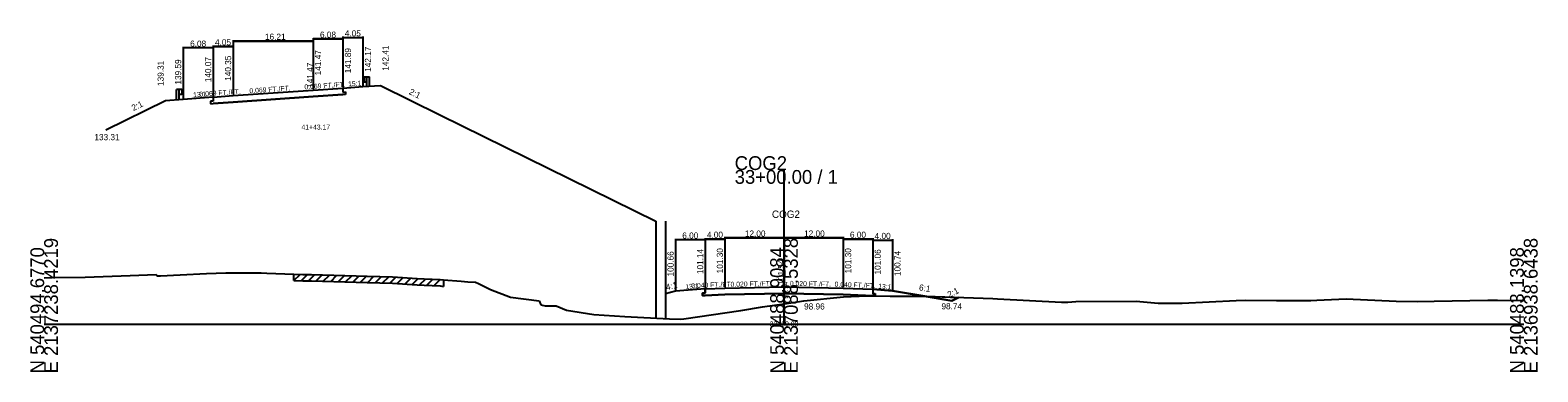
# Model space of a CAD drawing. Extents: x -13397 to 2303, y -10 to 39059.
# Drawn here: x 997.2 to 1302.8, y 5990.3 to 6059.6 of the extents above; entities that cross this region are included whole.
import ezdxf

# ---------------------------------------------------------------- set-up
doc = ezdxf.new("R2010")
doc.units = 0
for name, color, linetype in [('Level 20', 7, 'Continuous'), ('Level 5', 7, 'Continuous'), ('Level 53', 7, 'Continuous'), ('Level 54', 7, 'Continuous'), ('Level 55', 7, 'Continuous'), ('Level 7', 7, 'Continuous'), ('RD_GPK_XS_Cell', 7, 'Continuous'), ('RD_XS_EwShp', 7, 'Continuous'), ('RD_XS_ExGround', 7, 'Continuous'), ('RD_XS_ExPaveRet', 7, 'Continuous'), ('RD_XS_MedBWall', 7, 'Continuous'), ('RD_XS_Pave', 7, 'Continuous'), ('RD_XS_TX_Baseline', 7, 'Continuous'), ('RD_XS_TX_Elev_EX', 7, 'Continuous'), ('RD_XS_TX_Elev_PR', 7, 'Continuous'), ('RD_XS_TX_Station', 7, 'Continuous')]:
    doc.layers.add(name, color=color, linetype=linetype)

msp = doc.modelspace()

# ---------------------------------------------------------------- linework, layer by layer
at = {"layer": 'Level 20'}
for p, q in [((1028.17, 6056.22), (1028.17, 6045.79)), ((1034.25, 6056.02), (1028.17, 6056.02)), ((1034.25, 6056.5), (1034.25, 6046.27)), ((1034.25, 6056.5), (1034.25, 6046.27)), ((1034.25, 6056.5), (1034.25, 6046.27)), ((1034.25, 6056.3), (1038.3, 6056.3)), ((1034.25, 6056.3), (1038.3, 6056.3)), ((1038.3, 6056.3), (1034.25, 6056.3)), ((1034.25, 6056.22), (1034.25, 6046.27)), ((1038.3, 6057.62), (1038.3, 6046.55)), ((1038.3, 6057.62), (1038.3, 6046.55)), ((1038.3, 6057.62), (1038.3, 6046.55)), ((1038.3, 6057.62), (1038.3, 6046.55)), ((1038.3, 6057.42), (1054.51, 6057.42)), ((1038.3, 6057.42), (1054.51, 6057.42)), ((1054.51, 6057.42), (1038.3, 6057.42)), ((1054.51, 6057.42), (1038.3, 6057.42)), ((1038.3, 6056.5), (1038.3, 6046.55)), ((1038.3, 6056.5), (1038.3, 6046.55)), ((1038.3, 6056.5), (1038.3, 6046.55)), ((1054.51, 6058.04), (1054.51, 6047.67)), ((1054.51, 6058.04), (1054.51, 6047.67)), ((1054.51, 6058.04), (1054.51, 6047.67)), ((1054.51, 6057.84), (1060.58, 6057.84)), ((1060.58, 6057.84), (1054.51, 6057.84)), ((1060.58, 6057.84), (1054.51, 6057.84)), ((1054.51, 6057.62), (1054.51, 6047.67)), ((1054.51, 6057.62), (1054.51, 6047.67)), ((1054.51, 6057.62), (1054.51, 6047.67)), ((1054.51, 6057.62), (1054.51, 6047.67)), ((1060.58, 6058.32), (1060.58, 6048.09)), ((1060.58, 6058.12), (1064.63, 6058.12)), ((1060.58, 6058.04), (1060.58, 6048.09)), ((1060.58, 6058.04), (1060.58, 6048.09)), ((1060.58, 6058.04), (1060.58, 6048.09)), ((1064.63, 6058.32), (1064.63, 6048.37)), ((1064.66, 6049.99), (1064.77, 6050.08)), ((1064.66, 6049.88), (1064.77, 6049.79)), ((1064.66, 6049.46), (1064.77, 6049.55)), ((1064.79, 6050.08), (1064.86, 6050.1)), ((1064.79, 6049.75), (1064.79, 6049.59)), ((1064.86, 6050.16), (1064.86, 6049.18)), ((1064.86, 6050.16), (1065.42, 6050.16)), ((1065.42, 6048.17), (1065.42, 6050.16)), ((1065.42, 6050.16), (1065.97, 6050.16)), ((1065.97, 6048.17), (1065.97, 6050.16)), ((1026.83, 6045.59), (1026.83, 6047.58)), ((1027.39, 6047.58), (1026.83, 6047.58)), ((1027.39, 6045.59), (1027.39, 6047.58)), ((1027.94, 6047.58), (1027.39, 6047.58)), ((1027.94, 6046.6), (1027.39, 6046.6)), ((1027.94, 6047.58), (1027.94, 6046.6)), ((1028.02, 6047.5), (1027.94, 6047.52)), ((1028.02, 6046.68), (1027.94, 6046.66)), ((1028.01, 6047.17), (1028.01, 6047.01)), ((1028.15, 6047.41), (1028.03, 6047.5)), ((1028.15, 6047.3), (1028.03, 6047.21)), ((1028.15, 6046.88), (1028.03, 6046.97)), ((1028.15, 6046.77), (1028.03, 6046.68)), ((1038.3, 6046.35), (1054.51, 6047.47)), ((1054.51, 6047.47), (1060.58, 6047.89)), ((1060.58, 6046.56), (1054.51, 6046.14)), ((1054.51, 6046.14), (1060.58, 6046.56)), ((1054.51, 6046.14), (1060.58, 6046.56)), ((1060.58, 6047.89), (1064.63, 6048.17)), ((1060.58, 6047.89), (1060.58, 6047.06)), ((1060.58, 6047.06), (1061.09, 6047.09)), ((1061.09, 6046.59), (1060.58, 6046.56)), ((1061.09, 6047.09), (1061.09, 6046.59)), ((1064.63, 6048.17), (1068.18, 6048.41)), ((1064.66, 6049.36), (1064.77, 6049.26)), ((1064.79, 6049.26), (1064.86, 6049.25)), ((1064.86, 6049.18), (1065.42, 6049.18)), ((1068.18, 6048.41), (1080.33, 6042.41)), ((1024.62, 6045.31), (1012.47, 6039.31)), ((1028.17, 6045.59), (1024.62, 6045.31)), ((1034.25, 6046.07), (1028.17, 6045.59)), ((1034.25, 6045.24), (1033.74, 6045.2)), ((1033.74, 6045.2), (1033.74, 6044.7)), ((1033.74, 6044.7), (1034.25, 6044.74)), ((1034.25, 6046.07), (1038.3, 6046.35)), ((1034.25, 6046.07), (1034.25, 6045.24)), ((1038.3, 6045.02), (1034.25, 6044.74)), ((1038.3, 6045.02), (1034.25, 6044.74)), ((1034.25, 6044.74), (1038.3, 6045.02)), ((1054.51, 6046.14), (1038.3, 6045.02)), ((1054.51, 6046.14), (1038.3, 6045.02)), ((1038.3, 6045.02), (1054.51, 6046.14)), ((1038.3, 6045.02), (1054.51, 6046.14)), ((1080.33, 6042.41), (1124, 6020.85))]:
    msp.add_line(p, q, dxfattribs=at)
for centre, radius, start, end in [((1064.7, 6049.94), 0.0651, 129.0336, 230.9663), ((1064.7, 6049.41), 0.0651, 129.0336, 230.9663), ((1064.72, 6049.59), 0.0651, 302.9895, 0), ((1064.79, 6050.06), 0.026, 90, 129.0505), ((1064.72, 6049.75), 0.0651, 0, 45), ((1028.08, 6047.17), 0.0651, 135, 180), ((1028.08, 6047.01), 0.0651, 180, 237.0105), ((1028.02, 6047.48), 0.026, 50.9495, 90), ((1028.02, 6046.7), 0.026, 270, 309.0504), ((1028.1, 6047.35), 0.0651, 309.0337, 50.9664), ((1028.1, 6046.82), 0.0651, 309.0337, 50.9664), ((1064.79, 6049.28), 0.026, 230.9496, 270)]:
    msp.add_arc(centre, radius, start, end, dxfattribs=at)
at = {"layer": 'Level 5'}
for p, q in [((1134, 6007.14), (1134, 6006.31)), ((1168, 6007.06), (1168, 6006.23)), ((1134, 6006.31), (1133.5, 6006.29)), ((1133.5, 6006.29), (1133.5, 6005.79)), ((1133.5, 6005.79), (1134, 6005.81)), ((1138, 6005.97), (1134, 6005.81)), ((1138, 6005.97), (1134, 6005.81)), ((1138, 6005.97), (1134, 6005.81)), ((1134, 6005.81), (1138, 6005.97)), ((1150, 6006.21), (1138, 6005.97)), ((1150, 6006.21), (1138, 6005.97)), ((1150, 6006.21), (1138, 6005.97)), ((1138, 6005.97), (1150, 6006.21)), ((1138, 6005.97), (1150, 6006.21)), ((1162, 6005.97), (1150, 6006.21)), ((1162, 6005.97), (1150, 6006.21)), ((1150, 6006.21), (1162, 6005.97)), ((1150, 6006.21), (1162, 6005.97)), ((1150, 6006.21), (1162, 6005.97)), ((1168, 6005.73), (1162, 6005.97)), ((1162, 6005.97), (1168, 6005.73)), ((1162, 6005.97), (1168, 6005.73)), ((1162, 6005.97), (1168, 6005.73)), ((1168, 6006.23), (1168.5, 6006.21)), ((1168.5, 6005.71), (1168, 6005.73)), ((1168.5, 6006.21), (1168.5, 6005.71))]:
    msp.add_line(p, q, dxfattribs=at)
at = {"layer": 'Level 54'}
for p, q in [((1128, 6017.29), (1128, 6006.86)), ((1134, 6017.09), (1128, 6017.09)), ((1134, 6017.45), (1134, 6007.34)), ((1134, 6017.45), (1134, 6007.34)), ((1134, 6017.45), (1134, 6007.34)), ((1134, 6017.45), (1134, 6007.34)), ((1134, 6017.29), (1134, 6007.34)), ((1134, 6017.25), (1138, 6017.25)), ((1134, 6017.25), (1138, 6017.25)), ((1134, 6017.25), (1138, 6017.25)), ((1138, 6017.25), (1134, 6017.25)), ((1138, 6017.69), (1138, 6007.5)), ((1138, 6017.69), (1138, 6007.5)), ((1138, 6017.69), (1138, 6007.5)), ((1138, 6017.69), (1138, 6007.5)), ((1138, 6017.69), (1138, 6007.5)), ((1138, 6017.49), (1150, 6017.49)), ((1138, 6017.49), (1150, 6017.49)), ((1138, 6017.49), (1150, 6017.49)), ((1150, 6017.49), (1138, 6017.49)), ((1150, 6017.49), (1138, 6017.49)), ((1138, 6017.45), (1138, 6007.5)), ((1138, 6017.45), (1138, 6007.5)), ((1138, 6017.45), (1138, 6007.5)), ((1138, 6017.45), (1138, 6007.5)), ((1150, 6017.69), (1150, 6007.74)), ((1150, 6017.69), (1150, 6007.74)), ((1150, 6017.69), (1150, 6007.74)), ((1150, 6017.69), (1150, 6007.74)), ((1150, 6017.69), (1150, 6007.74)), ((1150, 6017.69), (1150, 6007.74)), ((1150, 6017.69), (1150, 6007.74)), ((1150, 6017.69), (1150, 6007.74)), ((1150, 6017.69), (1150, 6007.74)), ((1150, 6017.69), (1150, 6007.74)), ((1150, 6017.49), (1162, 6017.49)), ((1150, 6017.49), (1162, 6017.49)), ((1162, 6017.49), (1150, 6017.49)), ((1162, 6017.49), (1150, 6017.49)), ((1162, 6017.49), (1150, 6017.49)), ((1162, 6017.69), (1162, 6007.5)), ((1162, 6017.69), (1162, 6007.5)), ((1162, 6017.69), (1162, 6007.5)), ((1162, 6017.69), (1162, 6007.5)), ((1162, 6017.69), (1162, 6007.5)), ((1162, 6017.45), (1162, 6007.5)), ((1162, 6017.45), (1162, 6007.5)), ((1162, 6017.45), (1162, 6007.5)), ((1162, 6017.45), (1162, 6007.5)), ((1162, 6017.25), (1168, 6017.25)), ((1168, 6017.25), (1162, 6017.25)), ((1168, 6017.25), (1162, 6017.25)), ((1168, 6017.25), (1162, 6017.25)), ((1168, 6017.45), (1168, 6007.26)), ((1168, 6017.45), (1168, 6007.26)), ((1168, 6017.45), (1168, 6007.26)), ((1168, 6017.45), (1168, 6007.26)), ((1168, 6017.21), (1168, 6007.26)), ((1168, 6017.01), (1172, 6017.01)), ((1172, 6017.21), (1172, 6006.94))]:
    msp.add_line(p, q, dxfattribs=at)
at = {"layer": 'Level 7'}
for p, q in [((1128, 6006.66), (1126, 6006.16)), ((1134, 6007.14), (1128, 6006.66)), ((1168, 6007.06), (1172, 6006.74)), ((1172, 6006.74), (1184, 6004.74)), ((1126, 6006.16), (1126, 6001.12)), ((1184, 6004.74), (1185.37, 6005.42))]:
    msp.add_line(p, q, dxfattribs=at)
at = {"layer": 'RD_GPK_XS_Cell'}
for p, q in [((1150, 6000), (1150, 6031.26)), ((1000, 6000), (1150, 6000)), ((1150, 6000), (1300, 6000))]:
    msp.add_line(p, q, dxfattribs=at)
at = {"layer": 'RD_XS_EwShp'}
for points in [[(1166.8, 6005.73), (1168.5, 6005.71), (1168, 6005.73), (1162, 6005.97), (1150, 6006.21), (1138, 6005.97), (1134, 6005.81), (1133.5, 6005.79), (1133.5, 6006.29), (1134, 6006.31), (1134, 6007.14), (1128, 6006.66), (1126, 6006.16), (1126, 6001.12), (1126.8, 6001.08), (1128.96, 6000.99), (1129.68, 6001.05), (1141.23, 6002.79), (1145.66, 6003.48), (1150, 6004.14), (1154.01, 6004.74), (1162.04, 6005.54)], [(1168.5, 6006.21), (1168.5, 6005.71), (1171.55, 6005.65), (1177.75, 6005.65), (1178.57, 6005.64), (1172, 6006.74), (1168, 6007.06), (1168, 6006.23)], [(1178.57, 6005.64), (1178.77, 6005.64), (1185.37, 6005.42), (1184, 6004.74)]]:
    msp.add_lwpolyline(points, close=True, dxfattribs=at)
at = {"layer": 'RD_XS_ExGround'}
for p, q in [((1008.32, 6009.54), (1017.41, 6009.87)), ((1017.41, 6009.87), (1022.71, 6010.04)), ((1022.71, 6010.04), (1022.94, 6009.82)), ((1022.94, 6009.82), (1023.56, 6009.78)), ((1023.56, 6009.78), (1027.56, 6009.98)), ((1027.56, 6009.98), (1032.9, 6010.23)), ((1032.9, 6010.23), (1036.84, 6010.42)), ((1036.84, 6010.42), (1039.98, 6010.41)), ((1039.98, 6010.41), (1044.02, 6010.38)), ((1044.02, 6010.38), (1045.17, 6010.34)), ((1045.17, 6010.34), (1050.59, 6010.11)), ((1050.59, 6010.11), (1052.47, 6010.08)), ((1052.47, 6010.08), (1054.19, 6010.05)), ((1054.19, 6010.05), (1065.51, 6009.73)), ((1065.51, 6009.73), (1070.59, 6009.6)), ((1000, 6009.4), (1001.14, 6009.47)), ((1001.14, 6009.47), (1001.63, 6009.48)), ((1001.63, 6009.48), (1008.32, 6009.54)), ((1070.59, 6009.6), (1075.64, 6009.25)), ((1075.64, 6009.25), (1077.06, 6009.21)), ((1077.06, 6009.21), (1080.3, 6009.03)), ((1080.3, 6009.03), (1080.96, 6008.96)), ((1080.96, 6008.96), (1084.55, 6008.7)), ((1084.55, 6008.7), (1085.9, 6008.59)), ((1085.9, 6008.59), (1087.46, 6008.5)), ((1087.46, 6008.5), (1088.03, 6008.21)), ((1088.03, 6008.21), (1090.48, 6007.04)), ((1090.48, 6007.04), (1094.54, 6005.43)), ((1094.54, 6005.43), (1100.38, 6004.71)), ((1100.38, 6004.71), (1100.67, 6003.9)), ((1100.67, 6003.9), (1101.59, 6003.68)), ((1101.59, 6003.68), (1103.84, 6003.71)), ((1103.84, 6003.71), (1105.88, 6002.81)), ((1145.66, 6003.48), (1150, 6004.14)), ((1150, 6004.14), (1154.01, 6004.74)), ((1154.01, 6004.74), (1162.04, 6005.54)), ((1162.04, 6005.54), (1166.8, 6005.73)), ((1166.8, 6005.73), (1171.55, 6005.65)), ((1171.55, 6005.65), (1177.75, 6005.65)), ((1177.75, 6005.65), (1178.77, 6005.64)), ((1178.77, 6005.64), (1186.44, 6005.39)), ((1186.44, 6005.39), (1192.36, 6005.18)), ((1192.36, 6005.18), (1193.28, 6005.14)), ((1193.28, 6005.14), (1206.26, 6004.48)), ((1206.26, 6004.48), (1207.56, 6004.48)), ((1207.56, 6004.48), (1209.16, 6004.55)), ((1209.16, 6004.55), (1221.4, 6004.66)), ((1221.4, 6004.66), (1225.83, 6004.27)), ((1225.83, 6004.27), (1230.71, 6004.26)), ((1230.71, 6004.26), (1241.68, 6004.8)), ((1241.68, 6004.8), (1243.5, 6004.82)), ((1243.5, 6004.82), (1249.86, 6004.79)), ((1249.86, 6004.79), (1256.82, 6004.8)), ((1256.82, 6004.8), (1258.04, 6004.84)), ((1258.04, 6004.84), (1263.98, 6005.12)), ((1263.98, 6005.12), (1274.12, 6004.68)), ((1274.12, 6004.68), (1278.44, 6004.59)), ((1278.44, 6004.59), (1281.85, 6004.62)), ((1281.85, 6004.62), (1292.68, 6004.83)), ((1292.68, 6004.83), (1294.63, 6004.84)), ((1294.63, 6004.84), (1300, 6004.81)), ((1105.88, 6002.81), (1111.45, 6001.96)), ((1111.45, 6001.96), (1117.72, 6001.56)), ((1117.72, 6001.56), (1126.8, 6001.08)), ((1126.8, 6001.08), (1128.96, 6000.99)), ((1128.96, 6000.99), (1129.68, 6001.05)), ((1129.68, 6001.05), (1141.23, 6002.79)), ((1141.23, 6002.79), (1145.66, 6003.48))]:
    msp.add_line(p, q, dxfattribs=at)
at = {"layer": 'RD_XS_ExPaveRet'}
for p, q in [((1050.59, 6008.81), (1050.59, 6010.11)), ((1050.59, 6008.81), (1051.87, 6010.09)), ((1052.09, 6008.79), (1053.37, 6010.07)), ((1053.59, 6008.76), (1054.86, 6010.03)), ((1055.09, 6008.73), (1056.35, 6009.99)), ((1056.59, 6008.68), (1057.86, 6009.95)), ((1058.09, 6008.64), (1059.36, 6009.91)), ((1059.59, 6008.6), (1060.86, 6009.86)), ((1061.09, 6008.56), (1062.36, 6009.82)), ((1062.59, 6008.51), (1063.86, 6009.78)), ((1064.09, 6008.47), (1065.36, 6009.74)), ((1050.59, 6008.81), (1052.47, 6008.78)), ((1052.47, 6008.78), (1054.19, 6008.75)), ((1054.19, 6008.75), (1065.51, 6008.43)), ((1065.51, 6008.43), (1070.59, 6008.3)), ((1065.59, 6008.43), (1066.86, 6009.7)), ((1067.09, 6008.39), (1068.36, 6009.66)), ((1068.59, 6008.35), (1069.86, 6009.62)), ((1070.09, 6008.31), (1071.33, 6009.55)), ((1070.59, 6008.3), (1075.64, 6007.95)), ((1071.59, 6008.23), (1072.81, 6009.44)), ((1073.09, 6008.12), (1074.31, 6009.34)), ((1074.59, 6008.02), (1075.82, 6009.24)), ((1075.64, 6007.95), (1077.06, 6007.91)), ((1076.09, 6007.94), (1077.35, 6009.2)), ((1077.06, 6007.91), (1080.3, 6007.73)), ((1077.59, 6007.88), (1078.83, 6009.12)), ((1079.09, 6007.8), (1080.32, 6009.03)), ((1080.3, 6007.73), (1080.96, 6007.66)), ((1080.96, 6008.96), (1080.96, 6007.66))]:
    msp.add_line(p, q, dxfattribs=at)
at = {"layer": 'RD_XS_MedBWall'}
for p, q in [((1124, 6020.85), (1124, 6001.23)), ((1126, 6020.85), (1126, 6006.16))]:
    msp.add_line(p, q, dxfattribs=at)
at = {"layer": 'RD_XS_Pave'}
for p, q in [((1134, 6007.14), (1138, 6007.3)), ((1138, 6007.3), (1150, 6007.54)), ((1150, 6007.54), (1162, 6007.3)), ((1162, 6007.3), (1168, 6007.06))]:
    msp.add_line(p, q, dxfattribs=at)

# ---------------------------------------------------------------- texts
at = {"layer": 'Level 20'}
for s, height, p in [('16.21', 1.25, (1044.77, 6057.67)), ('16.21', 1.25, (1044.77, 6057.67)), ('16.21', 1.25, (1044.77, 6057.67)), ('16.21', 1.25, (1044.77, 6057.67)), ('6.08', 1.25, (1055.92, 6058.09)), ('6.08', 1.25, (1055.92, 6058.09)), ('6.08', 1.25, (1055.92, 6058.09)), ('4.05', 1.25, (1060.96, 6058.37)), ('6.08', 1.25, (1029.59, 6056.27)), ('4.05', 1.25, (1034.63, 6056.55)), ('4.05', 1.25, (1034.63, 6056.55)), ('4.05', 1.25, (1034.63, 6056.55)), ('41+43.17', 1, (1052.17, 6039.47)), ('133.31', 1.25, (1010.18, 6037.31))]:
    msp.add_text(s, height=height, dxfattribs=at).set_placement(p)
for s, height, rotation, p in [('141.89', 1.25, 90, (1062.22, 6050.89)), ('142.17', 1.25, 90, (1066.27, 6051.17)), ('142.41', 1.25, 90, (1069.82, 6051.41)), ('139.31', 1.25, 90, (1024.24, 6048.31)), ('139.59', 1.25, 90, (1027.78, 6048.59)), ('140.07', 1.25, 90, (1033.86, 6049.07)), ('140.35', 1.25, 90, (1037.91, 6049.35)), ('140.35', 1.25, 90, (1037.91, 6049.35)), (' 141.47', 1.25, 90, (1054.51, 6047.47)), ('141.47', 1.25, 90, (1056.15, 6050.47)), ('141.47', 1.25, 90, (1056.15, 6050.47)), ('13:1', 1, 4.5147, (1030.24, 6046)), ('0.069 FT./FT.', 1, 3.9582, (1031.53, 6046.13)), ('0.069 FT./FT.', 1, 3.9582, (1031.53, 6046.13)), ('0.069 FT./FT.', 1, 3.9582, (1031.53, 6046.13)), ('0.069 FT./FT.', 1, 3.9609, (1041.65, 6046.83)), ('0.069 FT./FT.', 1, 3.9609, (1041.65, 6046.83)), ('0.069 FT./FT.', 1, 3.9609, (1041.65, 6046.83)), ('0.069 FT./FT.', 1, 3.9609, (1041.65, 6046.83)), ('0.069 FT./FT.', 1, 3.9639, (1052.8, 6047.6)), ('0.069 FT./FT.', 1, 3.9639, (1052.8, 6047.6)), ('0.069 FT./FT.', 1, 3.9639, (1052.8, 6047.6)), ('15:1', 1, 3.9148, (1061.66, 6048.22)), ('2:1', 1.25, 333.7204, (1073.85, 6046.72)), ('2:1', 1.25, 26.2662, (1018.1, 6043.21))]:
    msp.add_text(s, height=height, rotation=rotation, dxfattribs=at).set_placement(p)
at = {"layer": 'Level 53'}
for s, rotation, p in [('100.66', 90, (1127.62, 6009.66)), ('101.14', 90, (1133.62, 6010.14)), ('101.30', 90, (1137.63, 6010.3)), ('101.30', 90, (1137.63, 6010.3)), ('101.30', 90, (1137.63, 6010.3)), ('101.30', 90, (1163.62, 6010.3)), ('101.30', 90, (1163.62, 6010.3)), ('101.30', 90, (1163.62, 6010.3)), ('101.06', 90, (1169.62, 6010.06)), ('100.74', 90, (1173.62, 6009.74)), ('4:1', 14.0362, (1126.21, 6006.83)), ('6:1', 350.5377, (1177.3, 6006.87))]:
    msp.add_text(s, height=1.25, rotation=rotation, dxfattribs=at).set_placement(p)
for s, p in [('98.96', (1154.07, 6002.96)), ('98.74', (1181.92, 6002.99))]:
    msp.add_text(s, height=1.25, dxfattribs=at).set_placement(p)
at = {"layer": 'Level 54'}
for s, p in [('12.00', (1142.07, 6017.74)), ('12.00', (1142.07, 6017.74)), ('12.00', (1142.07, 6017.74)), ('12.00', (1142.07, 6017.74)), ('12.00', (1142.07, 6017.74)), ('12.00', (1154.07, 6017.74)), ('12.00', (1154.07, 6017.74)), ('12.00', (1154.07, 6017.74)), ('12.00', (1154.07, 6017.74)), ('12.00', (1154.07, 6017.74)), ('6.00', (1129.37, 6017.34)), ('4.00', (1134.37, 6017.5)), ('4.00', (1134.37, 6017.5)), ('4.00', (1134.37, 6017.5)), ('4.00', (1134.37, 6017.5)), ('6.00', (1163.37, 6017.5)), ('6.00', (1163.37, 6017.5)), ('6.00', (1163.37, 6017.5)), ('6.00', (1163.37, 6017.5)), ('4.00', (1168.37, 6017.26))]:
    msp.add_text(s, height=1.25, dxfattribs=at).set_placement(p)
at = {"layer": 'Level 55'}
for s, height, rotation, p in [('13:1', 1, 4.5739, (1130.03, 6007.07)), ('0.040 FT./FT.', 1, 2.2906, (1131.22, 6007.28)), ('0.040 FT./FT.', 1, 2.2906, (1131.22, 6007.28)), ('0.040 FT./FT.', 1, 2.2906, (1131.22, 6007.28)), ('0.040 FT./FT.', 1, 2.2906, (1131.22, 6007.28)), ('0.020 FT./FT.', 1, 1.1458, (1139.17, 6007.57)), ('0.020 FT./FT.', 1, 1.1458, (1139.17, 6007.57)), ('0.020 FT./FT.', 1, 1.1458, (1139.17, 6007.57)), ('0.020 FT./FT.', 1, 1.1458, (1139.17, 6007.57)), ('0.020 FT./FT.', 1, 1.1458, (1139.17, 6007.57)), ('0.020 FT./FT.', 1, 358.8542, (1151.18, 6007.77)), ('0.020 FT./FT.', 1, 358.8542, (1151.18, 6007.77)), ('0.020 FT./FT.', 1, 358.8542, (1151.18, 6007.77)), ('0.020 FT./FT.', 1, 358.8542, (1151.18, 6007.77)), ('0.020 FT./FT.', 1, 358.8542, (1151.18, 6007.77)), ('0.040 FT./FT.', 1, 357.7094, (1160.24, 6007.62)), ('0.040 FT./FT.', 1, 357.7094, (1160.24, 6007.62)), ('0.040 FT./FT.', 1, 357.7094, (1160.24, 6007.62)), ('0.040 FT./FT.', 1, 357.7094, (1160.24, 6007.62)), ('13:1', 1, 355.4261, (1169.07, 6007.23)), ('2:1', 1.25, 26.5651, (1183.51, 6005.33))]:
    msp.add_text(s, height=height, rotation=rotation, dxfattribs=at).set_placement(p)
at = {"layer": 'RD_GPK_XS_Cell'}
for s, p in [('33+00.00 / 1', (1140, 6028.46)), ('COG2', (1140, 6031.26))]:
    msp.add_text(s, height=2.8, dxfattribs=at).set_placement(p)
for s, p in [('E 2137238.4219', (1002.8, 5990)), ('E 2137088.5328', (1152.8, 5990)), ('E 2136938.6438', (1302.8, 5990)), ('N 540494.6770', (1000, 5990)), ('N 540488.9084', (1150, 5990)), ('N 540483.1398', (1300, 5990))]:
    msp.add_text(s, height=2.8, rotation=90, dxfattribs=at).set_placement(p)
at = {"layer": 'RD_XS_TX_Baseline'}
msp.add_text('COG2', height=1.5, dxfattribs=at).set_placement((1147.55, 6021.54))
at = {"layer": 'RD_XS_TX_Elev_EX'}
msp.add_text('98.14', height=1, rotation=90, dxfattribs=at).set_placement((1150.75, 6005.14))
at = {"layer": 'RD_XS_TX_Elev_PR'}
msp.add_text(' 101.54', height=1.25, rotation=90, dxfattribs=at).set_placement((1150, 6007.54))
at = {"layer": 'RD_XS_TX_Station'}
msp.add_text('33+00.00', height=1, dxfattribs=at).set_placement((1147.11, 5999.54))

doc.saveas('drawing.dxf')
